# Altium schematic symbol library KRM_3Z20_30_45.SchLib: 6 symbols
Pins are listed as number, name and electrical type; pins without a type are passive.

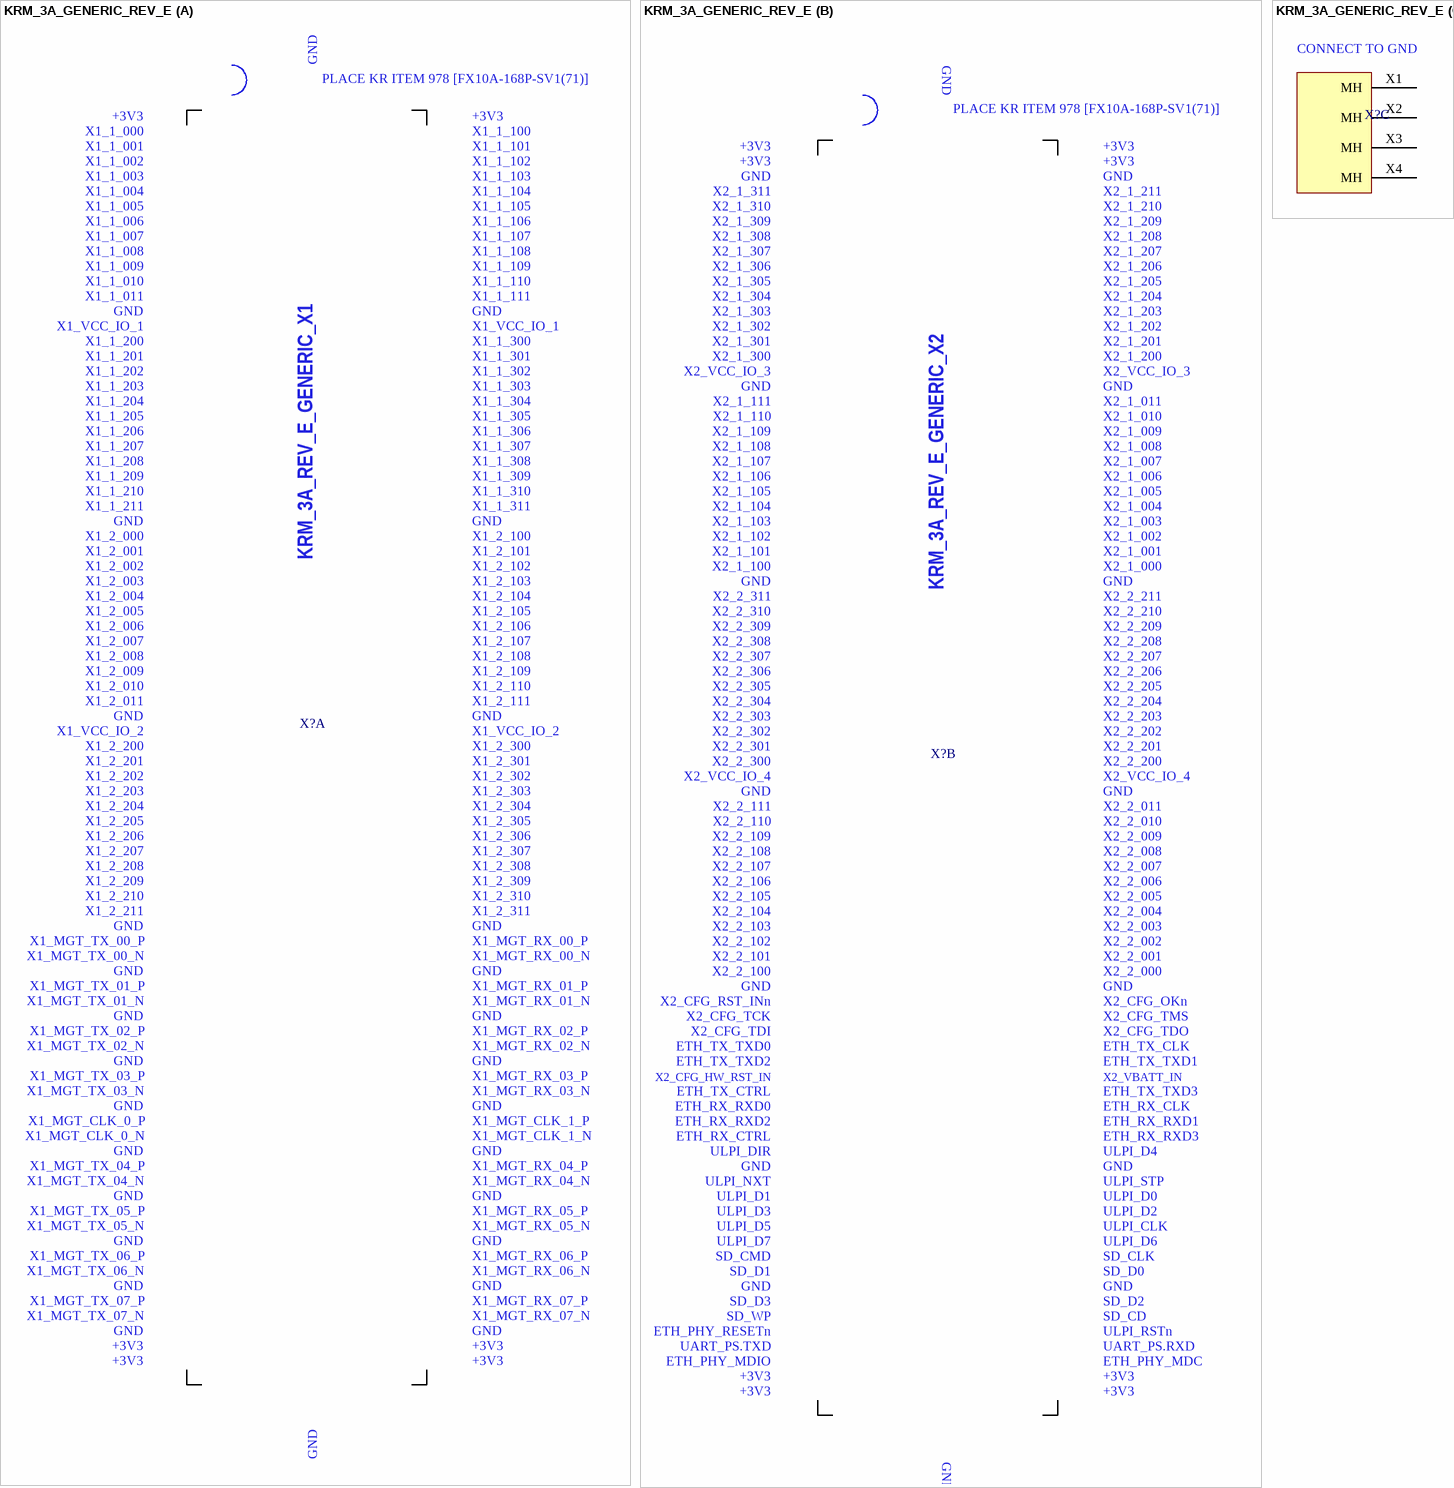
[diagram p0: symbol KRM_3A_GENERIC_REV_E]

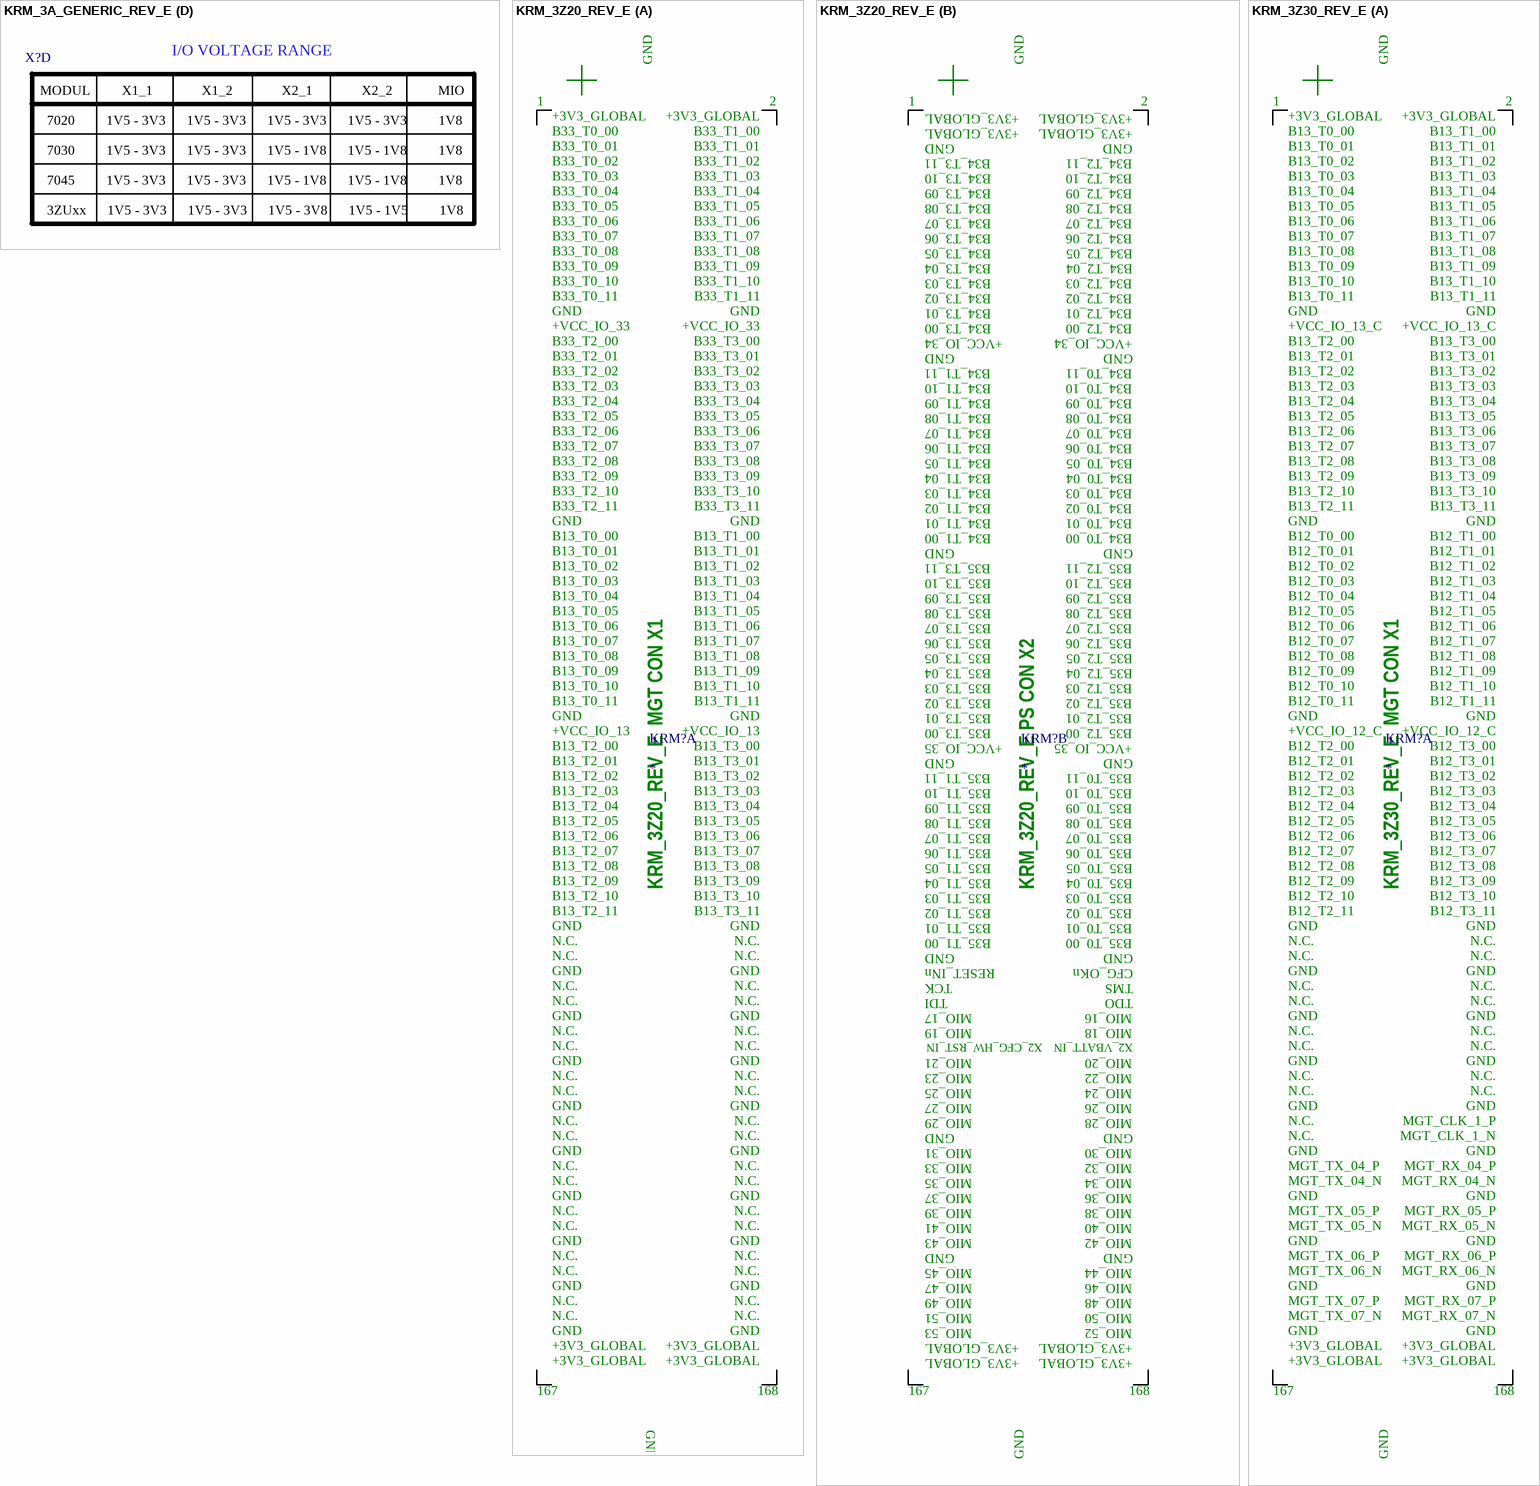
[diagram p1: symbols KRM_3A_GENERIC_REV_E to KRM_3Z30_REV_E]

## KRM_3A_GENERIC_REV_E
designator X?  (value not drawn)
168 PIN HEADER ASSIGNMENT
footprint KRM_3A_GENERIC (KR3000 series Module)
part C pins: X1 MH, X2 MH, X3 MH, X4 MH

## KRM_3Z20_REV_E
designator KRM?
COM/FPGA MODULE
footprint KRM_3Z20_REV_E (KR3000 series Module ZYNQ7020 VERSION_E)

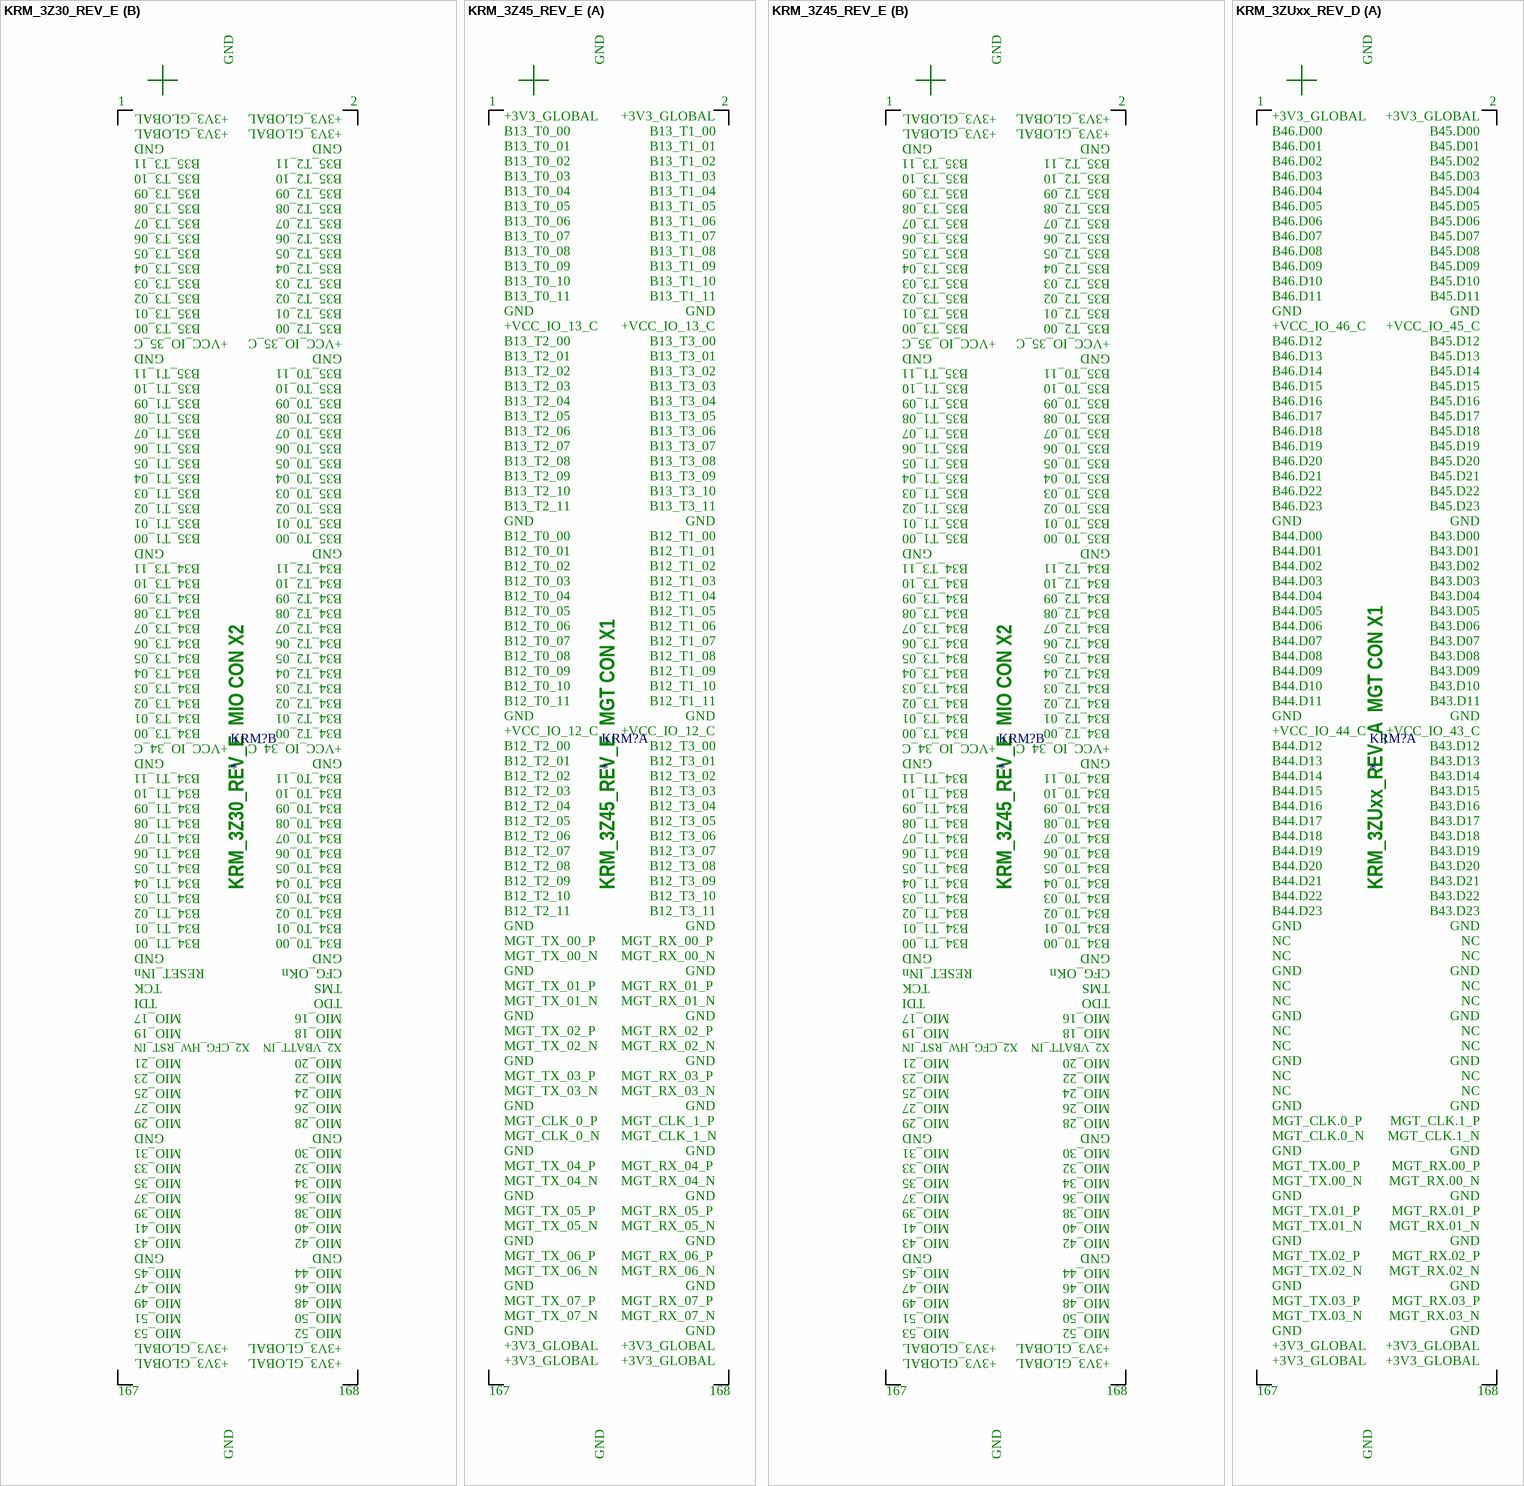
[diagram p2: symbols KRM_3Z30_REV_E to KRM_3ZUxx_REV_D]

## KRM_3Z30_REV_E
designator KRM?
COM/FPGA MODULE
footprint KRM_3Z30/45_REV_E (KR3000 series Module ZYNQ7030/45 VERSION_E)

## KRM_3Z45_REV_E
designator KRM?
COM/FPGA MODULE
footprint KRM_3Z30/45_REV_E (KR3000 series Module ZYNQ7030/45 VERSION_E)

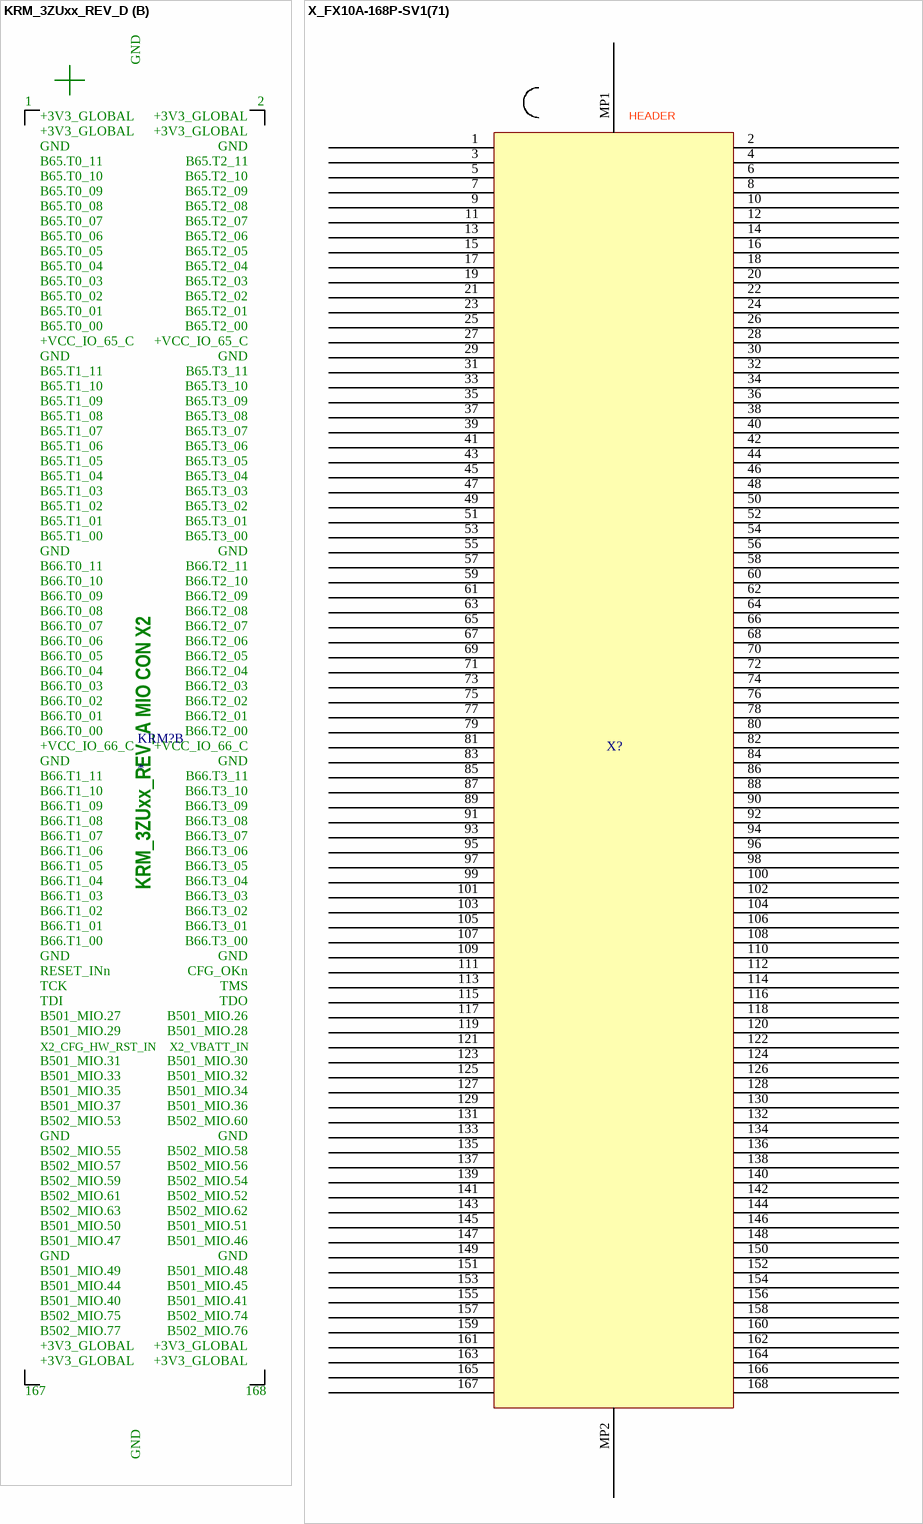
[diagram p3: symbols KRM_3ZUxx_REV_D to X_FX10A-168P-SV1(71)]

## KRM_3ZUxx_REV_D
designator KRM?
COM/FPGA MODULE with 3ZUxx FPGAs
footprint KRM_3ZUXX_REV_D (KR3000 series Module ZYNQ ZUxx VERSION_D)

## X_FX10A-168P-SV1(71)
designator X?  (value not drawn)
168 PIN HEADER
footprint X_FX10A-168P-SV1(71)
pins: 1, 2, 3, 4, 5, 6, 7, 8, 9, 10, 11, 12, 13, 14, 15, 16, 17, 18, 19, 20, 21, 22, 23, 24, 25, 26, 27, 28, 29, 30, 31, 32, 33, 34, 35, 36, 37, 38, 39, 40, 41, 42, 43, 44, 45, 46, 47, 48, 49, 50, 51, 52, 53, 54, 55, 56, 57, 58, 59, 60, 61, 62, 63, 64, 65, 66, 67, 68, 69, 70, 71, 72, 73, 74, 75, 76, 77, 78, 79, 80, 81, 82, 83, 84, 85, 86, 87, 88, 89, 90, 91, 92, 93, 94, 95, 96, 97, 98, 99, 100, 101, 102, 103, 104, 105, 106, 107, 108, 109, 110, 111, 112, 113, 114, 115, 116, 117, 118, 119, 120, 121, 122, 123, 124, 125, 126, 127, 128, 129, 130, 131, 132, 133, 134, 135, 136, 137, 138, 139, 140, 141, 142, 143, 144, 145, 146, 147, 148, 149, 150, 151, 152, 153, 154, 155, 156, 157, 158, 159, 160, 161, 162, 163, 164, 165, 166, 167, 168, MP1, MP2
